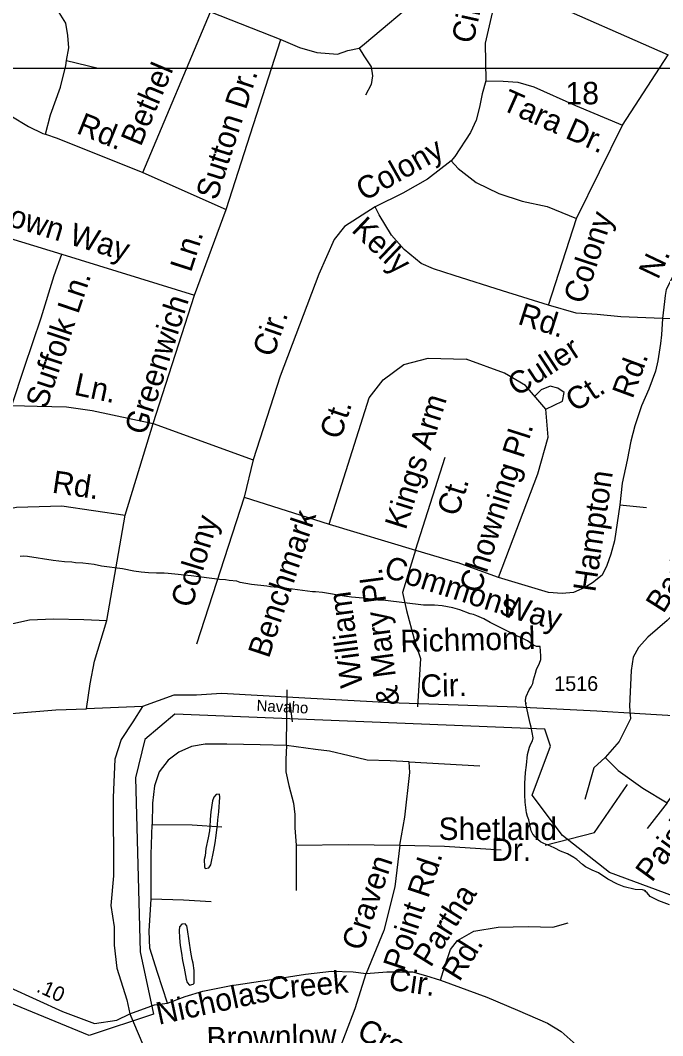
# Model space of a CAD drawing. Extents: x 2290055 to 2389491, y 66597 to 237875.
# Drawn here: x 2337738 to 2340457, y 152666 to 156961 of the extents above; entities that cross this region are included whole.
import ezdxf

# ---------------------------------------------------------------- set-up
doc = ezdxf.new("R2010")
doc.units = 0
for name, color, linetype in [('Exist Boundary Political City Limit New', 7, 'Continuous'), ('Exist Hydrographic Creek Single Shore', 7, 'Continuous'), ('Exist Hydrographic Pond Under 1500 Sq Ft', 7, 'Continuous'), ('Exist Road Non-System Type 51', 7, 'Continuous'), ('Exist Road Non-System Type 51 Label', 7, 'Continuous'), ('Exist Road Secondary Mileage Hundredths English Label', 7, 'Continuous'), ('Exist Road Secondary Type 51 Attributed', 7, 'Continuous'), ('Exist Road Secondary Type 51 Label', 7, 'Continuous'), ('Exist Road Secondary Type 51 Number Label', 7, 'Continuous'), ('Map Preparation Boundary City Limit Buffer Line', 7, 'Continuous'), ('Map Preparation Inset Cut Line', 7, 'Continuous')]:
    doc.layers.add(name, color=color, linetype=linetype)

msp = doc.modelspace()

# ---------------------------------------------------------------- linework, layer by layer
at = {"layer": 'Exist Boundary Political City Limit New'}
msp.add_lwpolyline([(2340503, 153256), (2340232, 153355.8), (2340032.5, 153512.7), (2339904.2, 153683.8), (2339982.5, 153890.6), (2339957.8, 153962.6), (2338392.2, 154026.4), (2338264.8, 153918.4), (2338225.5, 153756.4), (2338245.8, 153020.7), (2338302.5, 152756.7), (2338029.2, 152666.4), (2336836.8, 153157.4), (2336493.2, 153250.7), (2335452.8, 153697.5), (2335517.8, 156066.1), (2334898, 156075.8)], dxfattribs=at)
at = {"layer": 'Exist Hydrographic Creek Single Shore'}
for points in [[(2339877.7, 154073.5), (2339877.2, 154070.2), (2339877, 154085.8), (2339879, 154100.7), (2339892, 154129), (2339900.2, 154141.7), (2339907.7, 154155.9), (2339910.7, 154171), (2339919.5, 154200), (2339922.7, 154214.8), (2339935.7, 154242.5), (2339940.7, 154257.5), (2339941.2, 154273.5), (2339938.5, 154313.1), (2339923.5, 154312.8), (2339909.7, 154317.7), (2339885.2, 154336.9), (2339856.7, 154350), (2339845, 154354.2), (2339726.7, 154414.3), (2339699.5, 154429.4), (2339671, 154442.3), (2339656.7, 154447.2), (2339642, 154451.1), (2339598, 154467.6), (2339568.7, 154476.7), (2339523.7, 154484.4), (2339491.5, 154487.1), (2339445.5, 154486.9), (2339284.2, 154506.9), (2339251, 154509.2), (2339189, 154517.4), (2339140, 154521.2), (2339109, 154524.9), (2339017.7, 154541.6), (2338987.5, 154544.2), (2338974.5, 154544.3), (2338891, 154555.2), (2338875.2, 154556.4), (2338859.2, 154559.2), (2338812.7, 154563), (2338797, 154564.9), (2338782.2, 154567.9), (2338716.5, 154574.8), (2338669.5, 154583.6), (2338654.5, 154588.6), (2338623, 154592.1), (2338606.7, 154595.1), (2338581, 154595.3), (2338461.2, 154610.8), (2338363.5, 154621.1), (2338347, 154622.1), (2338314.7, 154622.2), (2338281.5, 154624.3), (2338250.2, 154627.6), (2338219.2, 154631.6), (2338170.5, 154641.5), (2338082.7, 154652.9), (2338051.2, 154659.9), (2338003.7, 154664.9), (2337971.7, 154666.5), (2337956.7, 154668.7), (2337925.5, 154671.2), (2337878, 154676.3), (2337769.2, 154693.9), (2337753.2, 154694.2), (2337738.2, 154693.5)], [(2340485.7, 153220.3), (2340440.7, 153237.1), (2340404.5, 153254.7), (2340391, 153271), (2340381.2, 153277.2), (2340385.5, 153278.3), (2340371, 153282.8), (2340340.2, 153285.1), (2340294.7, 153295.7), (2340280, 153301), (2340266.2, 153307.4), (2340224.5, 153328), (2340185.7, 153354.7), (2340158, 153366.8), (2340130.5, 153381.1), (2340117.2, 153389.8), (2340093.2, 153411.4), (2340080.7, 153420.4), (2340054, 153434.9), (2340024.7, 153447), (2340000, 153459.3), (2339982.7, 153467.4), (2339953.7, 153479.5), (2339940, 153486.7), (2339928, 153496.5), (2339917.2, 153507.1), (2339908.2, 153519.3), (2339900.5, 153532.6), (2339890, 153578.7), (2339884.7, 153593.1), (2339881, 153608.3), (2339875.7, 153654.5), (2339874.2, 153685.6), (2339873.7, 153732.8), (2339876.2, 153779.5), (2339880.7, 153810.3), (2339885.5, 153856.3), (2339893.5, 153886.1), (2339898.5, 153900.2), (2339905.5, 153914), (2339908.5, 153925.5), (2339901, 153971.1), (2339896, 153986.4), (2339877.2, 154070.2)]]:
    msp.add_lwpolyline(points, dxfattribs=at)
at = {"layer": 'Exist Hydrographic Pond Under 1500 Sq Ft'}
for points in [[(2338521.4, 153373.6), (2338536.1, 153376.3), (2338544.6, 153389.4), (2338557.9, 153451.3), (2338563.1, 153482.6), (2338567.6, 153513.6), (2338572.6, 153560.1), (2338573.9, 153579.3), (2338578.6, 153612.4), (2338582.9, 153674.9), (2338582.1, 153687.8), (2338567.1, 153686.6), (2338557.1, 153674.6), (2338551.4, 153660.3), (2338545.1, 153613.6), (2338541.6, 153580.8), (2338540.4, 153549.1), (2338538.6, 153533.1), (2338534.1, 153502.6), (2338523.9, 153457.6), (2338520.1, 153427.4), (2338517.1, 153411.8), (2338517.6, 153380.8), (2338521.4, 153373.6)], [(2338455, 152880.3), (2338470.2, 152883.9), (2338474.7, 152888.1), (2338474.7, 152942), (2338470.5, 152973.1), (2338466.2, 152987.9), (2338459.7, 153019.4), (2338446.5, 153115.4), (2338443, 153130.4), (2338435.5, 153139.7), (2338422, 153137.8), (2338411.5, 153126), (2338410.2, 153110.8), (2338411.7, 153079.4), (2338415.2, 153048.3), (2338421, 153015.4), (2338425, 152983.7), (2338431.7, 152952), (2338440, 152905.7), (2338445, 152891.1), (2338455, 152880.3)]]:
    msp.add_lwpolyline(points, dxfattribs=at)
at = {"layer": 'Exist Road Non-System Type 51'}
for p, q in [((2339784.1, 157122.8), (2340480, 156815.2)), ((2338256.4, 156317.1), (2338542.8, 156997.6)), ((2338542.8, 156997.6), (2338841.2, 156880.5)), ((2338609.7, 156160.6), (2338841.2, 156880.5)), ((2337934.5, 156791.6), (2338068, 156759.3)), ((2340287.7, 156517.8), (2340480, 156815.2)), ((2340092.5, 156122.5), (2340287.7, 156517.8)), ((2338256.4, 156317.1), (2338609.7, 156160.6)), ((2338475.6, 155798.6), (2338609.7, 156160.6)), ((2339973.2, 155756.9), (2340092.5, 156122.5)), ((2337914.1, 155971.9), (2338475.6, 155798.6)), ((2338301.3, 155255.3), (2338475.6, 155798.6)), ((2338181.6, 154867.7), (2338301.3, 155255.3)), ((2340275.5, 154911.4), (2340389, 154900.3)), ((2338105.3, 154423.1), (2338181.6, 154867.7)), ((2338865.3, 153894.3), (2338867.8, 154128.9)), ((2338256, 154058.8), (2338018, 154049.4)), ((2339384, 153824.5), (2339683.2, 153807))]:
    msp.add_line(p, q, dxfattribs=at)
for points in [[(2339172.4, 156844.3), (2339195.7, 156861.3), (2339434, 157062.9), (2339514.6, 157123.9), (2339543.7, 157137.1), (2339581.9, 157154.4), (2339632.3, 157165.3), (2339680.2, 157167.5), (2339784.1, 157122.8)], [(2339784.1, 157122.8), (2339747.7, 157049.8), (2339706.3, 156864.5), (2339708, 156705.5)], [(2337934.5, 156791.6), (2337943.9, 156844.8), (2337939.5, 156897.2), (2337930.8, 156949.5), (2337896, 157006.2), (2337883.5, 157032.6)], [(2338841.2, 156880.5), (2338919.9, 156847), (2338993.9, 156825.2), (2339081.1, 156818.7), (2339124.6, 156833.9), (2339172.4, 156844.3)], [(2339172.4, 156844.3), (2339191.7, 156811.3), (2339222.7, 156764.2), (2339229.2, 156727.1), (2339222.7, 156690), (2339198.7, 156644.3)], [(2341158.2, 156853.7), (2341084.1, 156818.4), (2341037.7, 156789.3), (2340988.9, 156758.4), (2340957.1, 156733.6), (2340928.9, 156701.9), (2340904.2, 156663), (2340879.5, 156620.6), (2340851.3, 156567.7), (2340823, 156500.6), (2340787.8, 156440.6), (2340581.9, 156066.5), (2340557, 156008.7), (2340521.8, 155925.2), (2340492.6, 155863.7), (2340472.4, 155823.2), (2340467.8, 155797.3), (2340464.3, 155772.6), (2340456.2, 155699.6)], [(2337845.3, 156479.3), (2337865.5, 156561.4), (2337909, 156679.1), (2337930.8, 156770.7), (2337934.5, 156791.6)], [(2337220.8, 156696.7), (2337266.9, 156700.5), (2337335.1, 156695.3), (2337446.5, 156665.6), (2337584.4, 156615.2), (2337698.9, 156557.7), (2337772.6, 156512.4), (2337833.8, 156483), (2337845.3, 156479.3)], [(2339708, 156705.5), (2339693.3, 156650.8), (2339682.4, 156594.1), (2339667.1, 156539.6), (2339643.1, 156487.3), (2339577.7, 156385.4), (2339562.4, 156367.1)], [(2339708, 156705.5), (2339781.5, 156704.2), (2339844.7, 156699.8), (2339912.2, 156680.2), (2340088.7, 156601.7), (2340287.7, 156517.8)], [(2337845.3, 156479.3), (2337894.7, 156463.4), (2338256.4, 156317.1)], [(2339562.4, 156367.1), (2339462.3, 156288.9), (2339357.8, 156230), (2339240, 156172.5)], [(2339562.4, 156367.1), (2339591.6, 156334.1), (2339667.1, 156275.8), (2339764.1, 156228.9), (2339862.1, 156196.2), (2339968.8, 156174.4), (2340092.5, 156122.5)], [(2339240, 156172.5), (2339110.7, 156089.1), (2339067.1, 156034.5), (2339001.8, 155887.3), (2338838.3, 155456.6), (2338723.9, 155102.1), (2338685.7, 154944), (2338484.1, 154322.4)], [(2339973.2, 155756.9), (2339779.3, 155816.8), (2339574.5, 155882.2), (2339487.4, 155910.6), (2339435.1, 155932.4), (2339363.2, 155991.3), (2339308.7, 156052.3), (2339257.1, 156139), (2339240, 156172.5)], [(2337486.9, 156101), (2337622.4, 156060.4), (2337914.1, 155971.9)], [(2337703.1, 155331.4), (2337756.8, 155493.7), (2337826.6, 155702.2), (2337881.5, 155882.6), (2337914.1, 155971.9)], [(2340456.2, 155699.6), (2340280, 155707.7), (2340180.2, 155716.5), (2340090.8, 155723.1), (2339973.2, 155756.9)], [(2340953.6, 155783.8), (2340918.3, 155780.2), (2340830.8, 155756.3), (2340770.1, 155736.1), (2340711.3, 155717.9), (2340660.7, 155705.7), (2340630.3, 155703.7), (2340555.4, 155697.6), (2340456.2, 155699.6)], [(2340456.2, 155699.6), (2340452.1, 155630.8), (2340448.1, 155594.3), (2340435.9, 155521.4), (2340426.3, 155477.4), (2340398, 155400.5), (2340367.1, 155331.1), (2340338.8, 155246), (2340322.6, 155181.2), (2340306.4, 155100.2), (2340286.1, 155003), (2340275.5, 154911.4)], [(2339045.3, 154829.5), (2339214.3, 155363.9), (2339274.2, 155440.2), (2339361.4, 155505.6), (2339464.9, 155532.9), (2339624.7, 155528.2)], [(2339761.6, 154604.1), (2339928.6, 155042.3), (2339973.1, 155198.1), (2339962, 155316.8), (2339876.7, 155416.9), (2339787.8, 155468.8), (2339624.7, 155528.2)], [(2339962, 155316.8), (2340032.4, 155350.1), (2340039.8, 155387.2), (2340013.9, 155405.8), (2339980.5, 155413.2), (2339943.4, 155398.4)], [(2339943.4, 155398.4), (2339915.9, 155370.8)], [(2337703.1, 155331.4), (2337809.5, 155329.7), (2337933.4, 155326.4), (2338042.3, 155310.7), (2338301.3, 155255.3)], [(2338301.3, 155255.3), (2338723.9, 155102.1)], [(2339410.4, 154720.4), (2339535.8, 155113)], [(2340924.7, 155115.2), (2340873, 154979.2), (2340784, 154823.5), (2340680.3, 154667.7), (2340576.5, 154519.3), (2340476.4, 154422.9), (2340394.9, 154352.4), (2340354.1, 154307.9), (2340331.9, 154267.1), (2340324.4, 154211.5), (2340317, 154059.4)], [(2338685.7, 154944), (2339045.3, 154829.5), (2339410.4, 154720.4), (2339587.6, 154667.7)], [(2337010.6, 154833.7), (2337148.4, 154793.2), (2337218.7, 154784.2), (2337272.8, 154786.3), (2337326, 154800.2), (2337454.8, 154839.4), (2337627, 154882), (2337722.4, 154901.9), (2337914.2, 154907.5), (2338181.6, 154867.7)], [(2340275.5, 154911.4), (2340253.7, 154760), (2340237.5, 154703.3), (2340221.3, 154654.7), (2340201.1, 154614.2), (2340160.6, 154581.8), (2340128.2, 154561.6), (2340079.6, 154541.3), (2340031, 154537.3), (2339974.3, 154541.3), (2339761.6, 154604.1)], [(2339410.4, 154720.4), (2339355.9, 154540.5), (2339372.3, 154464.1), (2339405, 154344.2), (2339432.2, 154262.4)], [(2339761.6, 154604.1), (2339587.6, 154667.7)], [(2337296.8, 154020.9), (2337306.6, 154179.1), (2337314.2, 154245.7), (2337328.6, 154278.1), (2337359.9, 154301.4), (2337430.5, 154332.1), (2337578.9, 154382.2), (2337777, 154425.8), (2337878.9, 154429.9), (2338007, 154427.1), (2338105.3, 154423.1)], [(2338018, 154049.4), (2338033.9, 154154.1), (2338052.1, 154250.6), (2338105.3, 154423.1)], [(2339432.2, 154262.4), (2339419.4, 154056.6)], [(2337700.8, 154028.7), (2337888.4, 154044), (2338018, 154049.4)], [(2338890.6, 153993.6), (2338880.6, 154073.7)], [(2340317, 154059.4), (2340320.8, 154006.3)], [(2340320.8, 154006.3), (2340272.6, 153910.3), (2340213.3, 153843.6), (2340165.1, 153799.1), (2340128, 153665.5)], [(2338865.3, 153894.3), (2338753.8, 153897.1), (2338612.9, 153899.8), (2338520.8, 153899.8), (2338462.6, 153889), (2338409.7, 153865.9), (2338363.7, 153832), (2338325.7, 153781.9), (2338306.8, 153723.6), (2338297.3, 153649.1), (2338296.7, 153560)], [(2338865.3, 153894.3), (2338862.8, 153834.5), (2338862.8, 153782.1), (2338875.2, 153724.7), (2338895.2, 153649.8), (2338900.2, 153602.4), (2338900.2, 153545), (2338905.2, 153472.7)], [(2339384, 153824.5), (2339304.2, 153829.5), (2339206.9, 153832), (2339129.6, 153849.4), (2339047.3, 153869.4), (2338987.5, 153876.9), (2338865.3, 153894.3)], [(2339344.1, 153472.7), (2339366.5, 153589.9), (2339386.5, 153779.6), (2339384, 153824.5)], [(2340213.3, 153843.6), (2340268.8, 153787.9), (2340372.6, 153713.8), (2340476.4, 153650.7), (2340539.4, 153739.7), (2340606.1, 153843.6)], [(2340476.4, 153650.7), (2340391.2, 153543.2)], [(2338291.7, 153245.6), (2338291.7, 153432.8), (2338296.7, 153560)], [(2338296.7, 153560), (2338466.3, 153557.5), (2338591, 153550)], [(2338905.2, 153472.7), (2339127.1, 153475.2), (2339344.1, 153472.7)], [(2338905.2, 153472.7), (2338905.2, 153360.4), (2338905.2, 153280.6)], [(2339344.1, 153472.7), (2339324.1, 153295.5), (2339276.7, 153110.9), (2339201.9, 152928.8)], [(2339344.1, 153472.7), (2339533.6, 153467.7), (2339773, 153452.7)], [(2338361.5, 152804), (2338319.2, 152933.7), (2338286.7, 153036), (2338284.2, 153108.4), (2338291.7, 153245.6)], [(2338291.7, 153245.6), (2338428.9, 153240.6), (2338546.1, 153233.2)], [(2339516.1, 152901.3), (2339533.6, 152956.2), (2339558.5, 153031.1), (2339588.4, 153068.5), (2339658.3, 153108.4), (2339760.5, 153125.9), (2339887.7, 153128.4), (2339992.4, 153125.9), (2340057.3, 153143.3)], [(2338361.5, 152804), (2338436.4, 152831.5), (2338511.2, 152853.9), (2338623.4, 152876.4), (2338783, 152901.3), (2338945.1, 152926.3), (2339054.8, 152938.7), (2339147.1, 152936.2), (2339201.9, 152928.8)], [(2339073.5, 152567), (2339155.8, 152781.6), (2339201.9, 152928.8)], [(2339201.9, 152928.8), (2339289.2, 152936.2), (2339398.9, 152936.2), (2339453.8, 152921.3), (2339516.1, 152901.3)], [(2339516.1, 152901.3), (2339713.1, 152829), (2339842.8, 152774.1), (2339970, 152719.2), (2340027.3, 152684.2), (2340090.9, 152626.9), (2340115.9, 152557), (2340113.4, 152489.6), (2340123.3, 152419.8), (2340143.3, 152364.9), (2340170.7, 152317.5), (2340188.2, 152285)], [(2338201.3, 152758.5), (2338306.7, 152796.5), (2338361.5, 152804)]]:
    msp.add_lwpolyline(points, dxfattribs=at)
at = {"layer": 'Exist Road Non-System Type 51 Label'}
msp.add_lwpolyline([(2339960.3, 153472.4), (2340168.3, 153525.8), (2340308.2, 153728.4)], dxfattribs=at)
at = {"layer": 'Exist Road Secondary Type 51 Attributed'}
for points in [[(2340619.4, 154012.2), (2340359.7, 154028.2), (2340178.6, 154039.4), (2339839.3, 154055.5), (2339301.6, 154074.7), (2339229.5, 154077.9), (2338943.1, 154093.4), (2338589.8, 154113), (2338484.5, 154107.1), (2338388.8, 154107.1), (2338256, 154058.8), (2338214.2, 153993.2), (2338165.3, 153919), (2338138.7, 153835.9), (2338131, 153673.8), (2338133.2, 153341.7), (2338121.5, 153216.7), (2338135.2, 153126.9), (2338135.2, 153048.8), (2338146.9, 152951.1), (2338189.8, 152818.4), (2338201.3, 152758.5)], [(2337153, 153058.8), (2337575.3, 152903.5), (2337694.5, 152870.2), (2337916.7, 152769), (2338052.6, 152718.3), (2338146.8, 152732.4), (2338201.3, 152758.5)], [(2338201.3, 152758.5), (2338271.8, 152591.9), (2338301, 152476.6), (2338396, 152217.8)]]:
    msp.add_lwpolyline(points, dxfattribs=at)
at = {"layer": 'Map Preparation Boundary City Limit Buffer Line'}
msp.add_lwpolyline([(2340503, 153256), (2340232, 153355.8), (2340032.5, 153512.7), (2339904.2, 153683.8), (2339982.5, 153890.6), (2339957.8, 153962.6), (2338392.2, 154026.4), (2338264.8, 153918.4), (2338225.5, 153756.4), (2338245.8, 153020.7), (2338302.5, 152756.7), (2338029.2, 152666.4), (2336836.8, 153157.4), (2336493.2, 153250.7), (2335452.8, 153697.5), (2335517.8, 156066.1), (2334898, 156075.8)], dxfattribs=at)
at = {"layer": 'Map Preparation Inset Cut Line'}
msp.add_lwpolyline([(2325416.4, 141886.2), (2343900.4, 141886.2), (2346064.1, 148689.8), (2346393.7, 149726.2), (2346064.1, 149726.2), (2346064.1, 156758), (2331912.3, 156758), (2331912.3, 149726.2), (2325417.5, 149726.2)], close=True, dxfattribs=at)

# ---------------------------------------------------------------- texts
at = {"layer": 'Exist Road Non-System Type 51 Label'}
for s, rotation, p in [('Cir.', 77.4097, (2339654.6, 156858.7)), ('Bethel', 67.174, (2338248, 156424)), ('Sutton Dr.', 72.1808, (2338569.6, 156196.4)), ('Tara Dr.', 336.0204, (2339769.2, 156586)), ('Rd.', 337.9712, (2337971.7, 156485.3)), ('Colony', 29.3775, (2339193.8, 156194.2)), ('Derby Down Way', 343.109, (2337237.9, 156228.6)), ('Colony', 71.9217, (2340124.9, 155756.9)), ('Kelly', 316.4258, (2339136, 156070.2)), ('Ln.', 72.1808, (2338460.4, 155891.8)), ('N.', 64.6265, (2340437.1, 155861.3)), ('Suffolk Ln.', 71.4786, (2337848.6, 155313.8)), ('Greenwich', 72.2092, (2338267.6, 155202.2)), ('Rd.', 342.2862, (2339839.3, 155678)), ('Cir.', 70.8193, (2338808.2, 155532.1)), ('Culler', 33.2204, (2339840.6, 155367.4)), ('Rd.', 69.775, (2340329.4, 155356.7)), ('Ln.', 347.9215, (2337961.7, 155378.3)), ('Ct.', 33.2204, (2340085.8, 155301.6)), ('Kings Arm', 72.5832, (2339369.5, 154802.1)), ('Ct.', 71.9786, (2339093, 155183.9)), ('Chowning Pl.', 72.3691, (2339684.6, 154532.4)), ('Rd.', 351.5376, (2337869.5, 154963.9)), ('Hampton', 81.6344, (2340171.6, 154539.8)), ('Ct.', 72.5832, (2339590.1, 154859)), ('Barksdale', 57.7809, (2340459.9, 154448.5)), ('Benchmark', 71.7159, (2338790, 154259.2)), ('Colony', 73.1483, (2338463.6, 154471.6)), ('Commons', 342.2612, (2339271.8, 154608.7)), ('& Mary Pl.', 97.4596, (2339343.8, 154068.1)), ('William', 97.4596, (2339188.3, 154144.8)), ('Way', 345.5697, (2339769.2, 154443.2)), ('Richmond', 1.3724, (2339347.6, 154288.1)), ('Cir.', 1.3724, (2339432.5, 154098.5)), ('Paisley Ct.', 53.8813, (2340411.4, 153311.5)), ('Craven', 71.5651, (2339186.1, 153020.4)), ('Point Rd.', 71.5651, (2339361.7, 152935.6)), ('Partha', 57.9944, (2339475, 152951.2)), ('Rd.', 57.9944, (2339596.5, 152890.8)), ('Creek', 5.1683, (2338791.5, 152818.2)), ('Cir.', 351.8699, (2339293.5, 152861.1)), ('Nicholas', 12.1893, (2338324.1, 152711.7)), ('Brownlow', 1.3784, (2338527.5, 152607.6)), ('Crown Point', 333.4351, (2339157.1, 152658.9))]:
    msp.add_text(s, height=95, rotation=rotation, dxfattribs=at).set_placement(p)
for s, p in [('18', (2340046.2, 156606)), ('Shetland', (2339508.4, 153494.1)), ('Dr.', (2339731.3, 153405.7))]:
    msp.add_text(s, height=95, dxfattribs=at).set_placement(p)
at = {"layer": 'Exist Road Secondary Mileage Hundredths English Label'}
msp.add_text('.10', height=62.5, rotation=335.5281, dxfattribs=at).set_placement((2337802.7, 152853.9))
at = {"layer": 'Exist Road Secondary Type 51 Label'}
msp.add_text('Navaho', height=47.5, rotation=357.1239, dxfattribs=at).set_placement((2338737.3, 154039.8))
at = {"layer": 'Exist Road Secondary Type 51 Number Label'}
msp.add_text('1516', height=62.5, dxfattribs=at).set_placement((2339998, 154124.5))

doc.saveas('drawing.dxf')
